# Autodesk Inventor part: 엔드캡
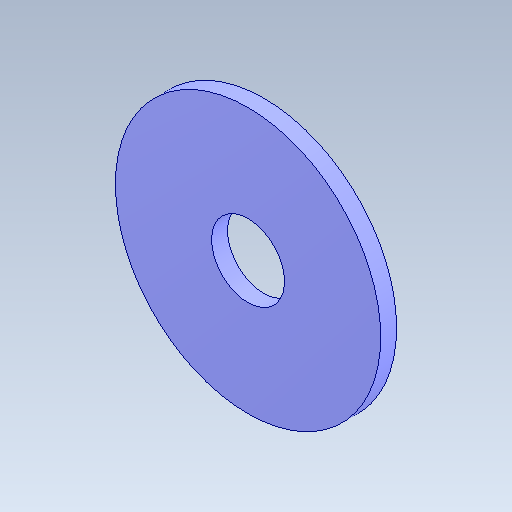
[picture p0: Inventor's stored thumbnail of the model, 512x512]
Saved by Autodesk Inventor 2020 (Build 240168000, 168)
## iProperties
Created: 2024-09
Part Number: 엔드캡
Material: 강철, 연강
Document SubType Name: Modeling
Designer: oem
Density: 7.85 g/cm^3
Appearance: 기본값
Author: jhkim
Sending System: Autodesk Inventor 2025
Preprocessor: ST-DEVELOPER v20
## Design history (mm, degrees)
feature "솔리드1"
node "솔리드2"
